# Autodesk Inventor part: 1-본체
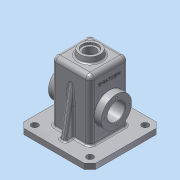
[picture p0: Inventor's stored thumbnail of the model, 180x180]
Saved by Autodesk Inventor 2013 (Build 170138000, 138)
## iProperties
Created: 2016-02
Part Number: 1-본체
Material: 알루미늄 6061
Document SubType Name: Modeling
Designer: ST1
Density: 2.71 g/cm^3
Mass: 934.659 g
Surface Area: 1035.22 cm^2
Volume: 344.892 cm^3
Author: ST1
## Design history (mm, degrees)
sketch "스케치1"
  geometry: L1 (65, -65)-(-65, -65); L2 (-65, -65)-(-65, 65); L3 (-65, 65)-(65, 65); L4 (65, 65)-(65, -65); 3 further points
  constraints: 8 end point, 2 midpoint, 2 parallel, 2 perpendicular, 1 horizontal, 1 horizontal alignment, 1 vertical alignment
  dimensions: "d0" = 130 distance of L2.end L3.end
extrude "돌출1" new body sketch "스케치1" distance "d3" = 10; taper "d4" = 0 deg
sketch "스케치2"
  geometry: L1 (-35, 35)-(35, 35); L2 (35, 35)-(35, -35); L3 (35, -35)-(-35, -35); L4 (-35, -35)-(-35, 35); 3 further points
  constraints: 8 end point, 2 midpoint, 2 parallel, 2 perpendicular, 1 horizontal, 1 horizontal alignment, 1 vertical alignment
  dimensions: "d5" = 70 distance of L1.start L1.end
extrude "돌출2" join sketch "스케치2" distance "d7" = 110; taper "d8" = 0 deg
fillet "모깎기2" dims "d18" = 8
sketch "스케치4"
  geometry: L1 (-30, 30)-(30, 30); L2 (30, 30)-(30, -30); L3 (30, -30)-(-30, -30); L4 (-30, -30)-(-30, 30); 3 further points
  constraints: 8 end point, 2 midpoint, 2 parallel, 2 perpendicular, 1 horizontal, 1 horizontal alignment, 1 vertical alignment
  dimensions: "d19" = 60 distance of L1.start L1.end
extrude "돌출3" cut sketch "스케치4" distance "d21" = 115; taper "d22" = 0 deg
sketch "스케치3"
  geometry: L1 (-35, 10)-(-35, 120) reference; L2 (65, 10)-(-65, 10) reference; L3 (-35, 95.069)-(-50, 10); L4 (-65, 0)-(-65, 10) reference; 1 further point
  constraints: 2 end point, 2 point on line
  dimensions: "d9" = 10 deg angle of L4 L3; "d10" = 15 distance of L2.end L3.end
feature "리브1" sketch "스케치3" dims "d11" = 1, "d12" = 10, "d13" = 0, "d14" = 0, "d15" = 1, "d16" = 1
sketch "스케치6"
  geometry: L1 (10, 100)-(10, -30) reference; C1 r 27.5 at (-45, 35); 2 further points
  constraints: 1 centre point, 1 horizontal alignment, 1 midpoint
  dimensions: "d27" = 55 distance from line of L1 C1.centre; "d28" = 55 diameter of C1
extrude "돌출4" join sketch "스케치6" distance "d29" = 13; taper "d30" = 0 deg
sketch "스케치7"
  geometry: C1 r 27.5 at (-55, 30) reference; 1 further point
extrude "돌출5" join sketch "스케치7" distance "d31" = 7; taper "d32" = -45 deg
sketch "스케치8"
  geometry: C1 r 27.5 at (0, 0) reference; C2 r 16 at (0, 0); 1 further point
  constraints: 1 centre point, 1 coincident
  dimensions: "d33" = 32 diameter of C2
extrude "돌출6" cut sketch "스케치8" stored distance "d35" = 7; taper "d36" = 0 deg
fillet "모깎기5" dims "d37" = 8
fillet "모깎기6" dims "d38" = 3
fillet "모깎기7" dims "d39" = 0.5
fillet "모깎기8" dims "d40" = 0.5
sketch "스케치9"
  geometry: C1 r 20 at (0, 0); 1 further point
  constraints: 1 centre point, 1 coincident
  dimensions: "d41" = 40 diameter of C1
extrude "돌출7" join sketch "스케치9" distance "d43" = 10; taper "d44" = -10 deg
sketch "스케치10"
  geometry: C1 r 18.237 at (0, 0) reference; C2 r 14 at (0, 0)
  constraints: 1 centre point, 1 coincident
  dimensions: "d45" = 28 diameter of C2
extrude "돌출8" cut sketch "스케치10" distance "d47" = 4; taper "d48" = 0 deg
sketch "스케치11"
  geometry: C1 r 14 at (0, 0) reference; C2 r 10.5 at (0, 0)
  constraints: 1 centre point, 1 coincident
  dimensions: "d49" = 21 diameter of C2
extrude "돌출9" cut sketch "스케치11" stored distance "d51" = 4; taper "d52" = 0 deg
fillet "모깎기9" dims "d53" = 3
chamfer "모따기1" distance "d54" = 10; stored, may be unused: second distance "d55" = 2, angle "d56" = 45 deg
sketch "스케치12"
  geometry: L1 (-65, 55)-(-65, -55) reference; L2 (55, 65)-(-55, 65) reference; C1 r 6 at (-50, -50); C2 r 6 at (-50, 50); C3 r 6 at (50, 50); C4 r 6 at (50, -50); 1 further point
  constraints: 4 centre point, 3 equal radius, 2 horizontal alignment, 2 vertical alignment
  dimensions: "d57" = 12 diameter of C2; "d59" = 15 distance from line of L2 C2.centre; "d60" = 100 distance of C1.centre C2.centre; "d61" = 15 distance from line of L1 C2.centre; "d62" = 100 distance of C3.centre C2.centre
extrude "돌출10" cut sketch "스케치12" stored distance "d63" = 4; taper "d64" = 0 deg
chamfer "모따기2" distance "d65" = 1; stored, may be unused: second distance "d66" = 2, angle "d67" = 45 deg
fillet "모깎기10" dims "d68" = 3
fillet "모깎기11" dims "d69" = 3
sketch "스케치13"
  geometry: L1 (99, 62)-(0, 62) reference; L2 (-18, 8.763)-(-18, 45.237) reference; 2 further points
  constraints: 1 other
  dimensions: "d70" = 35 distance from line of L1 point (12, 27); "d71" = 30 distance from line of L2 point (12, 27)
feature "엠보싱1" sketch "스케치13" dims "d0" = 130, "d72" = 0.5, "d73" = 0
sketch "스케치14"
  geometry: C1 r 27.5 at (0, 0) reference; 2 further points
  constraints: 1 horizontal alignment
  dimensions: "d74" = 22.5 distance of C1.centre point (-22.5, 0)
hole "구멍1" sketch "스케치14" at (-22.5, 0) diameter "d75" = 3.242; stored, may be unused: countersink angle "d79" = 90 deg, drill point angle "d81" = 118 deg; dims "d76" = 8, "d77" = 4, "d78" = 2, "d80" = 10
node "솔리드1"
mirror "대칭1"
mirror "대칭2"
mirror "대칭3"
pattern_circular "원형 패턴1" dims angle "d83" = 360 deg
mirror "대칭4"
